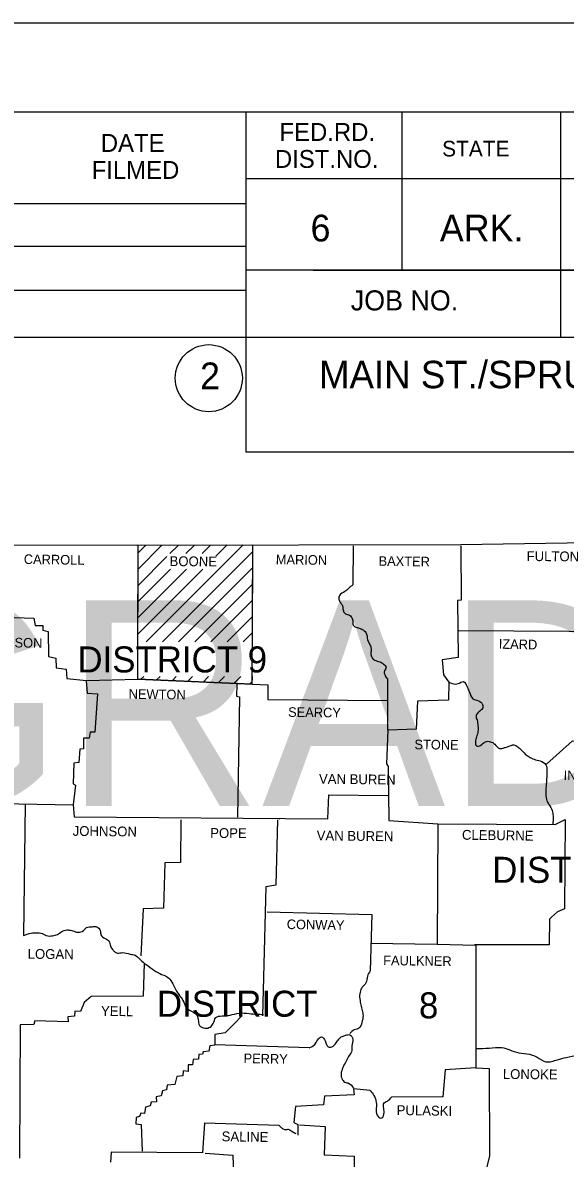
# Model space of a CAD drawing. Extents: x 19118 to 454486, y 1325406 to 1693506.
# Drawn here: x 26517 to 26754.5, y 1327042.2 to 1327539.3 of the extents above; entities that cross this region are included whole.
import ezdxf

# ---------------------------------------------------------------- set-up
doc = ezdxf.new("R2010")
doc.units = 0
for name, color, linetype in [('S_CURB', 7, 'Continuous'), ('S_EDGE_PAVEMENT', 7, 'Continuous'), ('S_PAVEMENT_CROWN', 7, 'Continuous'), ('S_SHOULDER', 7, 'Continuous')]:
    doc.layers.add(name, color=color, linetype=linetype)

msp = doc.modelspace()

# ---------------------------------------------------------------- linework, layer by layer
at = {"layer": 'S_CURB'}
for points in [[(26405.17, 1327310.68), (26566.87, 1327310.58), (26708.77, 1327310.88), (26876.16, 1327313.48), (26953.76, 1327315.28)], [(26496.42, 1327279.51), (26521.87, 1327278.68), (26522.47, 1327275.48), (26525.87, 1327275.38), (26525.77, 1327273.38), (26528.17, 1327272.78), (26528.37, 1327261.88), (26531.47, 1327261.18), (26531.67, 1327256.88), (26536.07, 1327256.28), (26536.27, 1327252.28), (26544.97, 1327251.38), (26567.37, 1327251.88), (26567.57, 1327310.58)], [(26567.47, 1327307.09), (26570.97, 1327310.59)], [(26567.47, 1327268.29), (26567.57, 1327310.59)], [(26567.57, 1327310.59), (26617.67, 1327310.79)], [(26567.57, 1327300.09), (26577.97, 1327310.59)], [(26571.07, 1327268.29), (26613.47, 1327310.69)], [(26581.47, 1327306.89), (26585.17, 1327310.59)], [(26588.47, 1327306.89), (26592.17, 1327310.59)], [(26595.57, 1327306.89), (26599.27, 1327310.59)], [(26601.57, 1327305.79), (26606.47, 1327310.69)], [(26617.67, 1327310.69), (26617.37, 1327250.18)], [(26617.67, 1327310.79), (26617.47, 1327268.29)], [(26661.67, 1327310.28), (26661.47, 1327293.18)], [(26708.77, 1327310.28), (26708.97, 1327286.48), (26707.27, 1327286.38), (26707.57, 1327261.48), (26700.57, 1327260.48), (26701.17, 1327253.78), (26703.57, 1327250.68), (26703.37, 1327242.78), (26689.77, 1327242.28), (26689.27, 1327230.08), (26676.87, 1327229.68), (26676.27, 1327214.88), (26676.97, 1327213.68), (26677.27, 1327190.08), (26698.67, 1327188.68), (26698.37, 1327135.98), (26715.37, 1327135.48), (26715.37, 1327081.88), (26701.97, 1327080.88), (26700.97, 1327069.08), (26678.47, 1327068.98)], [(26793.46, 1327312.2), (26793.66, 1327286.98), (26780.66, 1327286.28), (26780.26, 1327272.68), (26707.97, 1327273.08)], [(26567.57, 1327292.99), (26580.17, 1327305.59)], [(26578.17, 1327268.29), (26617.57, 1327307.69)], [(26567.47, 1327271.69), (26595.87, 1327300.09)], [(26567.47, 1327278.79), (26588.77, 1327300.09)], [(26567.57, 1327285.99), (26581.67, 1327300.09)], [(26585.17, 1327268.29), (26617.57, 1327300.69)], [(26592.37, 1327268.29), (26617.57, 1327293.49)], [(26599.37, 1327268.29), (26617.57, 1327286.49)], [(26606.47, 1327268.29), (26617.47, 1327279.29)], [(26613.57, 1327268.29), (26617.47, 1327272.19)], [(26489.89, 1327269.05), (26496.07, 1327269.08), (26487.97, 1327245.88), (26486.37, 1327208.78), (26485.17, 1327208.68), (26484.57, 1327197.48), (26490.47, 1327196.98), (26491.37, 1327197.88), (26539.07, 1327196.98), (26539.57, 1327191.68)], [(26544.77, 1327251.18), (26545.17, 1327245.78), (26549.77, 1327245.48), (26548.57, 1327228.68), (26546.47, 1327228.78), (26546.07, 1327226.08), (26543.67, 1327226.08), (26543.57, 1327221.48), (26542.07, 1327221.38), (26541.57, 1327215.48), (26539.37, 1327215.18), (26539.07, 1327206.18), (26540.07, 1327205.48), (26539.07, 1327196.98)], [(26567.37, 1327251.89), (26567.47, 1327253.09)], [(26617.37, 1327249.79), (26567.37, 1327251.89)], [(26567.37, 1327251.88), (26624.37, 1327249.48), (26624.27, 1327242.98), (26676.57, 1327242.58)], [(26568.77, 1327251.89), (26569.97, 1327253.09)], [(26575.57, 1327251.59), (26577.17, 1327253.09)], [(26582.37, 1327251.29), (26584.17, 1327253.09)], [(26589.17, 1327250.99), (26591.27, 1327253.09)], [(26595.97, 1327250.69), (26598.37, 1327253.09)], [(26602.77, 1327250.49), (26605.37, 1327253.09)], [(26609.57, 1327250.19), (26612.47, 1327253.09)], [(26616.37, 1327249.89), (26617.47, 1327250.99)], [(26617.47, 1327253.09), (26617.37, 1327249.79)], [(26676.87, 1327229.68), (26676.77, 1327252.18)], [(26610.67, 1327249.78), (26610.57, 1327244.58), (26611.87, 1327244.28), (26611.07, 1327191.48)], [(26746.27, 1327214.68), (26757.66, 1327224.98), (26793.66, 1327224.48), (26794.36, 1327217.78), (26807.46, 1327218.28)], [(26539.57, 1327191.68), (26650.57, 1327190.78), (26651.07, 1327201.28), (26676.87, 1327200.98)], [(26518.07, 1327197.38), (26517.37, 1327139.68)], [(26629.27, 1327190.68), (26629.57, 1327190.98)], [(26586.19, 1327190.42), (26586.09, 1327171.72), (26579.19, 1327171.62), (26578.59, 1327151.72), (26569.79, 1327151.42), (26568.79, 1327130.82)], [(26628.55, 1327190.31), (26627.81, 1327161.71), (26623.42, 1327160.98), (26621.95, 1327104.52)], [(26698.67, 1327188.68), (26750.07, 1327188.38), (26754.47, 1327190.48), (26754.17, 1327151.38), (26751.17, 1327150.08), (26748.47, 1327147.78), (26747.57, 1327146.88), (26747.47, 1327135.68), (26714.77, 1327135.68)], [(26624.07, 1327150.08), (26669.77, 1327148.98), (26669.17, 1327124.28)], [(26669.27, 1327136.38), (26698.37, 1327135.98)], [(26570.17, 1327127.58), (26569.77, 1327113.18), (26546.97, 1327113.08), (26543.97, 1327110.48), (26542.27, 1327106.48), (26539.77, 1327106.68), (26539.67, 1327104.38), (26536.77, 1327104.08), (26536.87, 1327101.98), (26522.37, 1327102.38), (26521.87, 1327100.78), (26515.87, 1327100.58), (26515.67, 1327042.23)], [(26613.07, 1327104.78), (26609.47, 1327100.88), (26605.57, 1327097.18), (26601.07, 1327096.48), (26601.07, 1327091.78), (26598.87, 1327091.48), (26598.47, 1327089.08), (26595.97, 1327088.88), (26595.77, 1327087.78), (26594.07, 1327087.68), (26593.97, 1327085.58), (26591.57, 1327085.48), (26591.37, 1327083.08), (26589.37, 1327083.08), (26589.47, 1327080.28), (26587.27, 1327080.48), (26587.17, 1327078.28), (26584.47, 1327078.08), (26583.67, 1327074.48), (26580.27, 1327074.18), (26579.97, 1327072.18), (26578.17, 1327071.68), (26577.67, 1327069.58), (26575.37, 1327069.08), (26575.57, 1327066.98), (26573.27, 1327066.78), (26572.87, 1327065.18), (26570.77, 1327064.58), (26570.27, 1327061.88), (26568.67, 1327061.98), (26568.17, 1327060.58), (26566.67, 1327060.08), (26566.57, 1327057.38), (26568.87, 1327056.98), (26569.27, 1327045.38)], [(26642.37, 1327090.58), (26601.17, 1327091.88)], [(26715.37, 1327081.88), (26721.17, 1327081.48), (26721.27, 1327043.28), (26716.07, 1327021.58), (26727.17, 1327021.08), (26727.06, 1327001.97)], [(26669.07, 1327071.88), (26661.87, 1327072.68), (26662.17, 1327069.98), (26649.07, 1327069.48), (26648.67, 1327065.58), (26636.37, 1327064.88), (26635.67, 1327057.88), (26637.47, 1327056.98), (26637.47, 1327052.38)], [(26700.57, 1327069.08), (26701.07, 1327069.58)], [(26629.27, 1327056.58), (26596.57, 1327057.58), (26595.67, 1327044.68), (26555.67, 1327044.88), (26555.5, 1327040.56)], [(26638.17, 1327056.88), (26649.37, 1327056.18), (26648.97, 1327043.68), (26662.07, 1327043.18), (26662.27, 1327032.28), (26668.47, 1327031.78), (26668.47, 1327029.88), (26674.27, 1327029.48), (26674.47, 1327022.48), (26687.67, 1327022.48), (26688.07, 1327015.58), (26700.27, 1327014.98), (26700.17, 1327001.98)], [(26596.87, 1327044.48), (26608.97, 1327043.58), (26609.37, 1327030.98), (26607.67, 1327030.38), (26607.47, 1327023.68), (26620.57, 1327022.78), (26620.57, 1327017.28), (26629.27, 1327016.78), (26629.37, 1327011.28), (26631.47, 1327010.98), (26631.37, 1327003.58)]]:
    msp.add_lwpolyline(points, dxfattribs=at)
for points in [[(26661.47, 1327293.18), (26659.67, 1327291.68), (26658.07, 1327290.28), (26655.67, 1327288.58), (26655.37, 1327286.98), (26656.17, 1327285.38), (26656.97, 1327284.08), (26657.27, 1327282.28), (26657.97, 1327280.78), (26659.67, 1327280.18), (26661.07, 1327278.88), (26661.57, 1327277.08), (26661.77, 1327275.38), (26663.37, 1327274.58), (26665.17, 1327273.98), (26666.87, 1327272.78), (26667.67, 1327271.28), (26667.87, 1327269.38), (26668.57, 1327267.88), (26669.37, 1327266.08), (26669.57, 1327264.58), (26669.37, 1327263.08), (26669.77, 1327261.68), (26671.07, 1327260.28), (26673.37, 1327259.58), (26674.97, 1327258.58), (26676.07, 1327257.18), (26675.37, 1327255.48), (26675.47, 1327253.98), (26676.37, 1327252.18)], [(26703.57, 1327250.68), (26707.57, 1327249.98), (26709.97, 1327250.88), (26711.67, 1327248.28), (26712.57, 1327246.28), (26714.07, 1327243.38), (26716.47, 1327242.48), (26718.27, 1327240.88), (26718.27, 1327239.18), (26716.67, 1327237.58), (26715.47, 1327235.98), (26715.87, 1327234.08), (26716.27, 1327231.48), (26716.27, 1327228.98), (26715.67, 1327226.68), (26715.17, 1327224.58), (26715.67, 1327222.78), (26717.57, 1327223.08), (26719.57, 1327224.58), (26721.67, 1327224.58), (26723.67, 1327223.48), (26725.77, 1327221.58), (26727.87, 1327221.98), (26729.57, 1327222.48), (26731.97, 1327223.18), (26733.67, 1327222.28), (26735.17, 1327221.08), (26736.97, 1327219.18), (26738.67, 1327217.98), (26740.87, 1327216.88), (26743.57, 1327216.18), (26746.07, 1327214.48), (26746.47, 1327211.58), (26746.37, 1327209.08), (26746.17, 1327205.98), (26745.97, 1327202.58), (26746.27, 1327199.28), (26747.37, 1327197.08), (26748.77, 1327194.48), (26749.17, 1327192.08), (26749.07, 1327188.28)], [(26517.37, 1327139.68), (26520.67, 1327140.78), (26523.07, 1327140.98), (26525.47, 1327140.58), (26527.97, 1327139.58), (26530.67, 1327139.78), (26532.67, 1327140.48), (26534.67, 1327141.78), (26536.87, 1327142.18), (26538.97, 1327141.78), (26541.17, 1327141.18), (26543.57, 1327141.88), (26544.97, 1327143.18), (26547.37, 1327143.58), (26549.47, 1327143.58), (26550.97, 1327141.88), (26551.27, 1327140.08), (26553.17, 1327138.38), (26554.87, 1327137.28), (26555.37, 1327135.18), (26556.27, 1327133.68), (26557.17, 1327132.68), (26558.47, 1327132.08), (26560.67, 1327132.28), (26564.07, 1327131.58), (26566.27, 1327131.08), (26568.27, 1327129.38), (26570.17, 1327127.58)], [(26570.17, 1327127.58), (26573.67, 1327125.18), (26576.97, 1327123.08), (26580.37, 1327121.58), (26582.27, 1327119.38), (26583.97, 1327115.98), (26585.37, 1327113.88), (26587.17, 1327111.28), (26588.47, 1327108.38), (26590.57, 1327106.78), (26592.77, 1327105.38), (26593.87, 1327102.88), (26594.37, 1327100.38), (26596.77, 1327099.18), (26599.07, 1327099.68), (26600.37, 1327101.18), (26601.57, 1327103.78), (26604.27, 1327104.58), (26607.77, 1327104.88), (26611.77, 1327105.78), (26616.17, 1327105.58), (26622.37, 1327105.18)], [(26669.17, 1327124.28), (26667.87, 1327121.98), (26667.27, 1327118.98), (26665.67, 1327117.08), (26664.67, 1327114.88), (26664.57, 1327111.98), (26665.07, 1327109.38), (26665.57, 1327106.88), (26665.97, 1327104.58), (26665.47, 1327101.68), (26664.17, 1327099.18), (26662.17, 1327098.48), (26660.27, 1327096.78)], [(26642.37, 1327090.58), (26644.87, 1327091.98), (26646.17, 1327094.08), (26647.77, 1327095.38), (26649.37, 1327093.58), (26650.77, 1327090.98), (26652.27, 1327090.98), (26654.17, 1327092.78), (26655.37, 1327094.38), (26656.87, 1327095.58), (26658.47, 1327096.08), (26660.17, 1327096.28), (26661.47, 1327094.38), (26661.07, 1327091.38), (26661.07, 1327089.38), (26659.97, 1327087.28), (26658.77, 1327085.08), (26657.47, 1327082.58), (26656.47, 1327079.88), (26656.67, 1327077.28), (26658.07, 1327075.58), (26659.67, 1327075.08), (26661.87, 1327072.88)], [(26715.57, 1327090.28), (26721.17, 1327090.48), (26726.67, 1327090.68), (26730.17, 1327089.68), (26734.17, 1327088.38), (26738.87, 1327087.78), (26742.17, 1327086.48), (26746.07, 1327084.48), (26751.07, 1327085.38), (26754.97, 1327086.38), (26760.06, 1327087.68), (26763.36, 1327089.08), (26767.16, 1327090.28), (26770.96, 1327089.78), (26775.26, 1327088.98), (26777.96, 1327087.38), (26782.86, 1327088.08), (26782.86, 1327094.28)], [(26669.07, 1327071.88), (26670.77, 1327069.68), (26671.77, 1327066.68), (26671.77, 1327063.28), (26672.57, 1327060.48), (26674.17, 1327059.88), (26675.17, 1327062.28), (26674.97, 1327064.68), (26674.97, 1327066.08), (26676.67, 1327067.28), (26678.47, 1327068.98)], [(26636.77, 1327052.88), (26634.87, 1327053.88), (26633.37, 1327054.78), (26631.77, 1327054.68), (26630.47, 1327055.48), (26629.27, 1327056.58)]]:
    msp.add_spline(points, degree=3, dxfattribs=at)
at = {"layer": 'S_EDGE_PAVEMENT'}
msp.add_lwpolyline([(23759.74, 1327539.29), (27093.14, 1327539.29), (27093.14, 1325405.92), (23759.74, 1325405.92)], close=True, dxfattribs=at)
at = {"layer": 'S_SHOULDER'}
for p, q in [((23883.81, 1327500.35), (27045.61, 1327500.35)), ((26614.61, 1327500.35), (26614.61, 1327351.45)), ((26683.01, 1327500.35), (26683.01, 1327430.95)), ((26752.41, 1327500.35), (26752.41, 1327401.55)), ((27045.61, 1327470.95), (26614.61, 1327470.95)), ((26223.01, 1327460.15), (26614.61, 1327460.15)), ((26223.01, 1327441.55), (26614.61, 1327441.55)), ((27045.61, 1327430.95), (26614.61, 1327430.95)), ((26644.21, 1327430.95), (27045.61, 1327430.95)), ((26223.01, 1327422.15), (26614.61, 1327422.15)), ((27045.61, 1327401.55), (26223.01, 1327401.55)), ((26614.61, 1327351.45), (27045.61, 1327351.45))]:
    msp.add_line(p, q, dxfattribs=at)
msp.add_circle((26598.48, 1327383.7), 14.67, dxfattribs=at)

# ---------------------------------------------------------------- texts
at = {"layer": 'S_CURB'}
for s, height, rotation, p in [('CARROLL', 4.201, 359.1481, (26517.47, 1327302.38)), ('BOONE', 4.301, 359.4001, (26581.27, 1327301.48)), ('MARION', 4.201, 359.1854, (26627.77, 1327302.28)), ('BAXTER', 4.201, 359.2559, (26672.77, 1327301.58)), ('FULTON', 4.3, 359.4996, (26737.57, 1327303.68)), ('MADISON', 4.201, 359.0906, (26499.37, 1327266.08)), ('IZARD', 4.199, 358.9258, (26725.37, 1327265.28)), ('NEWTON', 4.201, 359.2717, (26563.37, 1327243.38)), ('SEARCY', 4.199, 359.2527, (26633.17, 1327235.48)), ('STONE', 4.199, 359.4001, (26688.47, 1327221.28)), ('VAN BUREN', 4.301, 359.3452, (26646.67, 1327206.18)), ('INDEPENDENCE', 4.1993, 359.2187, (26753.77, 1327207.78)), ('JOHNSON', 4.301, 359.3514, (26538.87, 1327183.38)), ('POPE', 4.301, 359.6155, (26599.07, 1327182.48)), ('VAN BUREN', 4.301, 359.3508, (26645.67, 1327181.38)), ('CLEBURNE', 4.3, 359.2535, (26709.27, 1327181.68)), ('CONWAY', 4.199, 359.0371, (26632.57, 1327142.58)), ('LOGAN', 4.301, 359.3969, (26519.17, 1327129.58)), ('FAULKNER', 4.201, 359.2486, (26674.77, 1327126.78)), ('YELL', 4.301, 359.1987, (26551.27, 1327104.58)), ('PERRY', 4.2, 359.0858, (26613.67, 1327083.88)), ('LONOKE', 4.301, 359.4974, (26727.17, 1327076.98)), ('PULASKI', 4.301, 359.053, (26680.67, 1327061.18)), ('SALINE', 4.301, 359.1491, (26604.07, 1327049.68))]:
    msp.add_text(s, height=height, rotation=rotation, dxfattribs=at).set_placement(p)
for s, height, p in [('MAIN ST.   SPRUCE ST. SIGNAL UPGRADE', 89.9998, (24421.67, 1327196.45)), ('DISTRICT 9', 11.4, (26540.97, 1327254.88)), ('DISTRICT', 11.4, (26722.52, 1327162.8)), ('DISTRICT', 11.4, (26575.77, 1327104.18)), ('8', 11.4, (26690.47, 1327103.48))]:
    msp.add_text(s, height=height, dxfattribs=at).set_placement(p)
at = {"layer": 'S_PAVEMENT_CROWN'}
msp.add_text('MAIN ST./SPRUCE ST. SIGNAL UPGRADE', height=12, dxfattribs=at).set_placement((26646.7, 1327379.3))
at = {"layer": 'S_SHOULDER'}
for s, height, p in [('FED.RD.', 7.819, (26629.41, 1327487.55)), ('DATE', 7.819, (26551.21, 1327482.75)), ('STATE', 6.84, (26700.61, 1327480.75)), ('DIST.NO.', 7.819, (26627.41, 1327475.75)), ('FILMED', 7.819, (26547.21, 1327470.95)), ('6', 11.72, (26643.01, 1327443.55)), ('ARK.', 11.723, (26699.61, 1327443.55)), ('JOB NO.', 8.792, (26660.61, 1327413.35)), ('2', 11.72, (26594.65, 1327378.84))]:
    msp.add_text(s, height=height, dxfattribs=at).set_placement(p)

doc.saveas('drawing.dxf')
